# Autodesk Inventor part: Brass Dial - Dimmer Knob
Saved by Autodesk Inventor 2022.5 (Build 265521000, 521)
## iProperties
Created: 2024-07
Part Number: Brass Dial - Dimmer Knob
Material: Generic
Document SubType Name: Modeling
Designer: AdminForWorker
Density: 1 g/cm^3
Appearance: Default
Title: Brass Dial - Dimmer Knob
Author: AdminForWorker
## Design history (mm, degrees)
feature "Brass Dial - Dimmer Knob"
body "Solid1"
